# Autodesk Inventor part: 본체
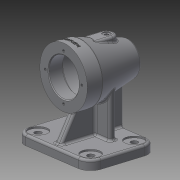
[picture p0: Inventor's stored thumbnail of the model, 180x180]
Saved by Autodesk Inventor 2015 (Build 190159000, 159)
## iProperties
Created: 2024-12
Part Number: 본체
Material: 알루미늄 6061
Document SubType Name: Modeling
Designer: 102566
Density: 2.7 g/cm^3
Appearance: 기본값
Mass: 753.502 g
Surface Area: 670.934 cm^2
Volume: 279.075 cm^3
Author: 102566
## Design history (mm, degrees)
sketch "스케치1"
  geometry: L1 (57, 44.5)-(-57, 44.5); L2 (-57, 44.5)-(-57, -44.5); L3 (-57, -44.5)-(57, -44.5); L4 (57, -44.5)-(57, 44.5); L5 (57, 44.5)-(-57, -44.5); L6 (-57, 44.5)-(57, -44.5); 1 further point
  constraints: 12 end point, 2 midpoint, 2 parallel, 1 horizontal, 1 perpendicular
  dimensions: "d0" = 114 distance of L2.end L3.end; "d1" = 89 distance of L3.end L1.start
extrude "돌출1" new body sketch "스케치1" distance "d2" = 12; taper "d3" = 0 deg
sketch "스케치3"
  geometry: L1 (82, 35.374)-(82, -61.09); L2 (82, 29.5)-(119, 29.5); L3 (119, 29.5)-(119, 9.5); L4 (0, 44.5)-(0, -44.5) reference; L5 (0, 44.5)-(12, 44.5) reference; L6 (119, 9.5)-(103, -54.5); L7 (103, -54.5)-(82, -54.5); 1 further point
  constraints: 10 end point, 2 perpendicular, 2 point on line, 1 horizontal, 1 vertical
  dimensions: "d7" = 119 distance between parallel lines of L4 L3; "d8" = 15 distance between parallel lines of L5 L2; "d11" = 20 distance of L2.end L3.end; "d12" = 84 distance between parallel lines of L7 L2; "d13" = 74 diameter of L3 L1; "d15" = 21 distance of L6.end L7.end
revolve "회전1" sketch "스케치3" stored, may be unused: angle "d16" = 90 deg
sketch "스케치4"
  geometry: L1 (57, 44.5)-(-57, 44.5) reference; L2 (-28, 15.5)-(28, 15.5); L3 (28, 15.5)-(28, 7.5); L4 (28, 7.5)-(-28, 7.5); L5 (-28, 7.5)-(-28, 15.5); 1 further point
  constraints: 8 end point, 2 parallel, 1 horizontal, 1 perpendicular
  dimensions: "d17" = 29 distance between parallel lines of L1 L2; "d18" = 8 distance of L4.end L2.start; "d19" = 56 distance of L2.start L2.end; "d20" = 28 distance from line of point (0, 0) L3
extrude "돌출2" join sketch "스케치4" stored distance "d21" = 18; taper "d22" = 0 deg
sketch "스케치5"
  geometry: L1 (57, 44.5)-(-57, 44.5) reference; L2 (-5, 44.5)-(5, 44.5); L3 (5, 44.5)-(5, 11.5); L4 (5, 11.5)-(-5, 11.5); L5 (-5, 11.5)-(-5, 44.5); 1 further point
  constraints: 8 end point, 2 parallel, 1 horizontal, 1 perpendicular, 1 point on line
  dimensions: "d23" = 10 distance of L3.end L4.end; "d24" = 5 distance from line of point (0, 0) L3; "d25" = 33 distance of L2.end L3.end
extrude "돌출3" join sketch "스케치5" stored distance "d26" = 18; taper "d27" = 0 deg
node "작업 평면2"
sketch "스케치6"
  geometry: L1 (7, 12)-(33.995, 58.757); L2 (33.995, 58.757)-(62.56, 58.757); L3 (62.56, 58.757)-(62.56, 12); L4 (7, 12)-(62.56, 12); L5 (89, 12)-(0, 12) reference; L6 (0, 0)-(0, 12) reference; L7 (89, 0)-(0, 0) reference; 1 further point
  constraints: 8 end point, 1 collinear, 1 horizontal, 1 perpendicular
  dimensions: "d29" = 7 distance from line of L6 L1.start; "d30" = 60 deg angle of L4 L1; "d31" = 28.56483 distance of L1.end L2.end; "d32" = 46.75708 distance of L2.end L3.end; "d33" = 12 distance between parallel lines of L7 L4
extrude "돌출4" join sketch "스케치6" stored distance "d34" = 10; taper "d35" = 0 deg
sketch "스케치7"
  geometry: L1 (15, 82)-(99, 82); L2 (15, 82)-(15, 105.5); L3 (33, 105.5)-(33, 107.489); L4 (39.29, 112.32)-(78, 101.981); L5 (78, 101.981)-(78, 99.5); L6 (78, 99.5)-(88, 99.5); L7 (88, 99.5)-(88, 97.5); L8 (88, 97.5)-(91, 97.5); L9 (91, 97.5)-(91, 82); L10 (33, 105.5)-(15, 105.5); L11 (89, 0)-(0, 0) reference; L12 (99, 61)-(99, 103) reference; A1 r 5 centre (38, 107.489) between (39.29, 112.32) and (33, 107.489); 2 further points
  constraints: 20 end point, 5 perpendicular, 3 point on line, 2 point on circle, 2 tangent, 1 centre point, 1 parallel, 1 vertical
  dimensions: "d36" = 47 diameter of L10 L1; "d37" = 45 distance between parallel lines of L5 L3; "d38" = 18 distance of L3.start L2.end; "d39" = 10 distance of L5.end L6.end; "d40" = 3 distance of L7.end L8.end; "d41" = 35 diameter of L6 L1; "d42" = 31 diameter of L8 L1; "d43" = 64 diameter of point (33, 114) L1; "d45" = 82 distance between parallel lines of L11 L1; "d99" = 5 radius of A1; "d100" = 90 deg angle of L10 L2; "d101" = 8 distance between parallel lines of L12 L9; "d102" = 104.954 deg angle of L5 L4
revolve "회전2" sketch "스케치7" stored, may be unused: angle "d46" = 90 deg
sketch "스케치8"
  geometry: L1 (-57, 44.5)-(-57, -44.5) reference; L2 (-57, -44.5)-(57, -44.5) reference; 2 further points
  dimensions: "d47" = 16 distance from line of L2 point (-41, -28.5); "d48" = 16 distance from line of L1 point (-41, -28.5)
hole "구멍1" sketch "스케치8" at (-41, -28.5) diameter "d49" = 9; stored, may be unused: countersink angle "d53" = 90 deg, drill point angle "d55" = 0 deg; dims "d50" = 6, "d51" = 24, "d52" = 2, "d54" = 8
sketch "스케치9" dims "d62" = 57
  geometry: C1 r 23.5 at (0, 0) reference; C2 r 37 at (0, 0) reference; 3 further points
  constraints: 2 vertical alignment, 1 coincident, 2 other
hole "구멍2" sketch "스케치9" at (0, 28.5) diameter "d63" = 3.242; stored, may be unused: countersink angle "d67" = 90 deg, drill point angle "d69" = 118 deg; dims "d64" = 8, "d65" = 24, "d66" = 2, "d68" = 10
node "작업 평면3"
sketch "스케치10"
  geometry: L1 (-10, 3.5)-(10, 3.5); L2 (10, 3.5)-(10, -36.5); L3 (10, -36.5)-(-10, -36.5); L4 (-10, -36.5)-(-10, 3.5); L5 (-37, 29.5)-(37, 29.5) reference; 1 further point
  constraints: 8 end point, 2 parallel, 1 horizontal, 1 perpendicular
  dimensions: "d74" = 20 distance of L2.end L3.end; "d75" = 66 distance between parallel lines of L5 L3; "d76" = 10 distance from line of point (0, 0) L2; "d77" = 40 distance of L1.end L2.end
extrude "돌출5" join sketch "스케치10" stored distance "d78" = 10; taper "d79" = 0 deg
fillet "모깎기1" dims "d80" = 16
fillet "모깎기2" dims "d81" = 3
fillet "모깎기3" dims "d82" = 3
fillet "모깎기4" dims "d83" = 3
sketch "스케치11"
  geometry: L1 (37, -29.5)-(-37, -29.5) reference; 2 further points
  dimensions: "d84" = 56 distance from line of L1 point (0, 26.5)
hole "구멍3" sketch "스케치11" at (0, 26.5) diameter "d85" = 4.917; stored, may be unused: countersink angle "d89" = 90 deg, drill point angle "d91" = 0 deg; dims "d86" = 12, "d87" = 10, "d88" = 1, "d90" = 17.1
fillet "모깎기5" dims "d92" = 10
fillet "모깎기6" dims "d93" = 3
node "작업 평면5"
sketch "스케치13"
  geometry: 3 further points
  constraints: 1 vertical alignment, 1 other
feature "엠보싱1" sketch "스케치13" dims "d0" = 114, "d1" = 89, "d96" = 0.5, "d97" = 0
fillet "모깎기7" dims "d98" = 0.3
fillet "모깎기8" dims "d103" = 3
chamfer "모따기1" distance "d104" = 1; stored, may be unused: second distance "d105" = 2, angle "d106" = 45 deg
fillet "모깎기9" dims "d107" = 3
fillet "모깎기10" dims "d108" = 3
fillet "모깎기11" dims "d109" = 3
node "솔리드1"
pattern_linear "직사각형 패턴1" dims "d58" = 57, "d61" = 82
pattern_circular "원형 패턴1" dims angle "d71" = 360 deg
other parameters: "d28" = -57, "d73" = -115
